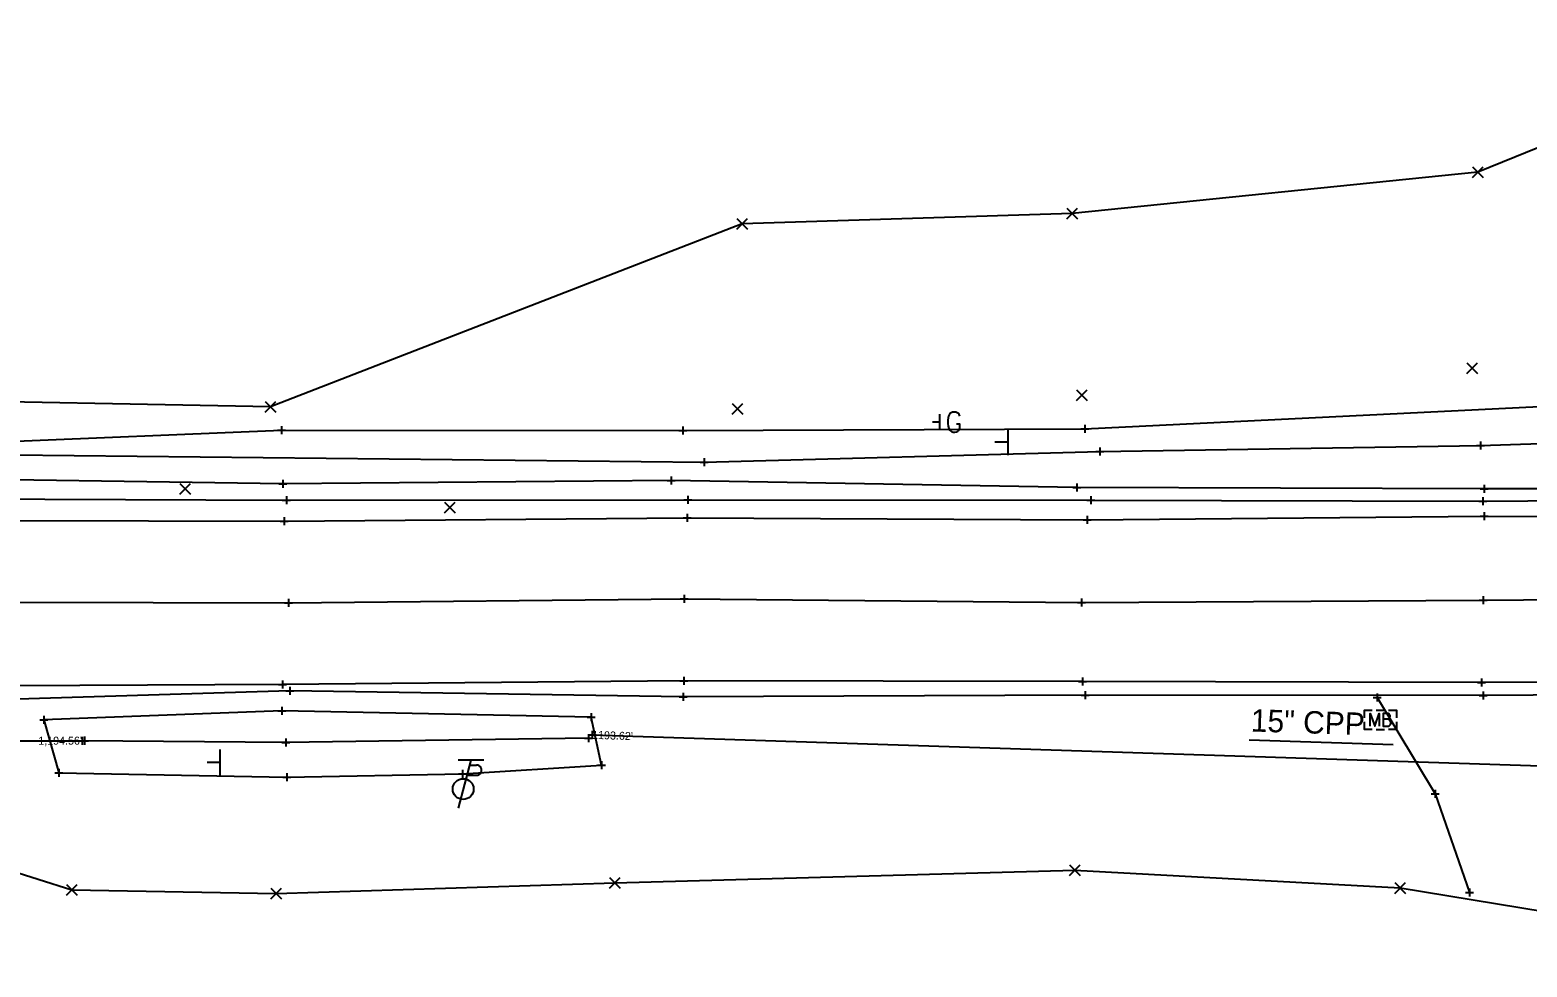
# Model space of a CAD drawing. Extents: x 2319153 to 2321514, y 575338 to 575500.
# Drawn here: x 2320483 to 2320670.1, y 575366.1 to 575483.2 of the extents above; entities that cross this region are included whole.
import ezdxf

# ---------------------------------------------------------------- set-up
doc = ezdxf.new("R2010")
doc.units = 0
for name, color, linetype in [('Default', 7, 'Continuous'), ('DR_X_Ditch', 7, 'Continuous'), ('DR_X_Elev_Flow', 7, 'Continuous'), ('DR_X_Storm_Sewer', 7, 'Continuous'), ('DR_X_Text', 7, 'Continuous'), ('PV_X_COP', 7, 'Continuous'), ('PV_X_Driveway', 7, 'Continuous'), ('PV_X_EOP', 7, 'Continuous'), ('PV_X_Shoulder', 7, 'Continuous'), ('RD_X_Cells', 7, 'Continuous'), ('SC_Scratch1', 7, 'Continuous'), ('SN_X_Public', 7, 'Continuous'), ('SV_X_Break_Lines', 7, 'Continuous'), ('SV_X_Random_Point', 7, 'Continuous'), ('SV_X_Shot_Marker', 7, 'Continuous'), ('SV_X_Terrain_Boundary', 7, 'Continuous'), ('UT_X_Gas_Cells', 7, 'Continuous'), ('UT_X_Misc_Cells', 7, 'Continuous')]:
    doc.layers.add(name, color=color, linetype=linetype)

msp = doc.modelspace()

# ---------------------------------------------------------------- linework, layer by layer
at = {"layer": 'Default'}
msp.add_line((2320553.26, 575395.15), (2320553.26, 575395.15), dxfattribs=at)
at = {"layer": 'DR_X_Ditch'}
for points in [[(2320442.27, 575427.97), (2320464.89, 575430.3), (2320567.27, 575429.23), (2320616.67, 575430.56), (2320664.25, 575431.29), (2320715.69, 575433.03), (2320722.62, 575480.62)], [(2320552.81, 575394.74), (2320515, 575394.2), (2320489.55, 575394.38)]]:
    msp.add_lwpolyline(points, dxfattribs=at)
at = {"layer": 'DR_X_Elev_Flow'}
for p, q in [((2320489.84, 575394.92), (2320489.84, 575393.92)), ((2320552.76, 575395.15), (2320553.76, 575395.15)), ((2320553.26, 575395.65), (2320553.26, 575394.65)), ((2320553.26, 575395.15), (2320553.26, 575395.15)), ((2320489.34, 575394.42), (2320490.34, 575394.42)), ((2320489.84, 575394.42), (2320489.84, 575394.42))]:
    msp.add_line(p, q, dxfattribs=at)
at = {"layer": 'DR_X_Storm_Sewer'}
for p, q in [((2320553.26, 575395.15), (2320731.3, 575389.3)), ((2320445.01, 575394.3), (2320489.84, 575394.42))]:
    msp.add_line(p, q, dxfattribs=at)
at = {"layer": 'DR_X_Text'}
msp.add_line((2320653.33, 575393.89), (2320635.36, 575394.48), dxfattribs=at)
at = {"layer": 'PV_X_COP'}
msp.add_lwpolyline([(2320114.93, 575411.33), (2320165.7, 575411.06), (2320216.04, 575411.34), (2320265.84, 575411.19), (2320315.14, 575411.25), (2320365.04, 575411.47), (2320415.78, 575411.96), (2320464.61, 575411.79), (2320515.32, 575411.65), (2320564.75, 575412.16), (2320614.38, 575411.69), (2320664.58, 575411.98), (2320714.9, 575412.38)], dxfattribs=at)
at = {"layer": 'PV_X_Driveway'}
msp.add_lwpolyline([(2320651.34, 575399.8), (2320658.59, 575387.79), (2320662.88, 575375.45)], dxfattribs=at)
at = {"layer": 'PV_X_EOP'}
for points in [[(2320093.83, 575421.33), (2320165.53, 575421.34), (2320217.08, 575420.91), (2320266.56, 575421.33), (2320315.91, 575421.64), (2320365.38, 575421.59), (2320416.21, 575421.87), (2320463.92, 575421.98), (2320514.77, 575421.86), (2320565.11, 575422.28), (2320615.12, 575422), (2320664.7, 575422.48), (2320715.11, 575422.41)], [(2320714.4, 575401.87), (2320664.35, 575401.67), (2320614.5, 575401.81), (2320564.7, 575401.89), (2320514.59, 575401.42), (2320463.88, 575401.2), (2320414.8, 575400.99), (2320364.6, 575400.96), (2320315.2, 575400.77), (2320265.49, 575400.71), (2320215.68, 575400.77), (2320165.34, 575400.63), (2320115.4, 575400.66)]]:
    msp.add_lwpolyline(points, dxfattribs=at)
at = {"layer": 'PV_X_Shoulder'}
for points in [[(2320077.57, 575423.62), (2320166.34, 575422.88), (2320218.2, 575423.13), (2320266.92, 575423.62), (2320316.5, 575423.54), (2320365.74, 575423.49), (2320415.91, 575423.76), (2320464.74, 575424.68), (2320515.05, 575424.47), (2320565.23, 575424.51), (2320615.54, 575424.46), (2320664.52, 575424.33), (2320715.19, 575424.71)], [(2320714.58, 575400.4), (2320664.56, 575400.05), (2320614.84, 575400.09), (2320564.64, 575399.89), (2320515.49, 575400.65), (2320463.79, 575399.05), (2320414.96, 575398.83), (2320364.78, 575399.66), (2320315.61, 575399.52), (2320265.3, 575399.56), (2320215.74, 575399.78), (2320165.72, 575399.22), (2320115.8, 575398.99)]]:
    msp.add_lwpolyline(points, dxfattribs=at)
at = {"layer": 'RD_X_Cells'}
for p, q in [((2320651.22, 575398.24), (2320652.23, 575398.24)), ((2320651.74, 575397.02), (2320651.74, 575397.02)), ((2320651.22, 575395.8), (2320652.23, 575395.8))]:
    msp.add_line(p, q, dxfattribs=at)
for points in [[(2320649.74, 575397.27), (2320649.74, 575398.24), (2320650.71, 575398.24)], [(2320650.71, 575395.8), (2320649.74, 575395.8), (2320649.74, 575396.77)], [(2320650.44, 575396.22), (2320650.44, 575397.82), (2320651.02, 575396.22), (2320651.57, 575397.82), (2320651.57, 575396.22)], [(2320652.76, 575397.09), (2320652.82, 575397.15), (2320652.86, 575397.19), (2320652.88, 575397.23), (2320652.9, 575397.25), (2320652.92, 575397.31), (2320652.93, 575397.34), (2320652.96, 575397.43), (2320652.96, 575397.47), (2320652.96, 575397.52), (2320652.95, 575397.59), (2320652.92, 575397.66), (2320652.88, 575397.71), (2320652.82, 575397.76), (2320652.77, 575397.78), (2320652.75, 575397.8), (2320652.68, 575397.82), (2320652.07, 575397.82), (2320652.07, 575396.22), (2320652.76, 575396.22), (2320652.85, 575396.27), (2320652.92, 575396.34), (2320652.98, 575396.44), (2320653.02, 575396.55), (2320653.04, 575396.66), (2320653.04, 575396.74), (2320653.01, 575396.81), (2320652.96, 575396.93), (2320652.9, 575397), (2320652.76, 575397.09), (2320652.07, 575397.09)], [(2320652.74, 575398.24), (2320653.74, 575398.24), (2320653.74, 575397.27)], [(2320653.74, 575396.77), (2320653.74, 575395.8), (2320652.74, 575395.8)]]:
    msp.add_lwpolyline(points, dxfattribs=at)
at = {"layer": 'SN_X_Public'}
for p, q in [((2320605.18, 575433.31), (2320605.18, 575430.11)), ((2320605.18, 575431.71), (2320603.58, 575431.71)), ((2320506.74, 575393.31), (2320506.74, 575390.11)), ((2320506.74, 575391.71), (2320505.14, 575391.71))]:
    msp.add_line(p, q, dxfattribs=at)
at = {"layer": 'SV_X_Break_Lines'}
msp.add_lwpolyline([(2320732.93, 575442.06), (2320727.34, 575431.55), (2320720.41, 575425.89), (2320664.7, 575425.9), (2320613.83, 575426.05), (2320563.12, 575426.93), (2320514.6, 575426.5), (2320463.64, 575427.26), (2320441.18, 575426.16), (2320442.02, 575430.24), (2320514.44, 575433.22), (2320564.58, 575433.19), (2320614.81, 575433.37), (2320685.2, 575436.83)], dxfattribs=at)
msp.add_lwpolyline([(2320486.63, 575390.39), (2320515.13, 575389.87), (2320537.05, 575390.29), (2320554.44, 575391.36), (2320553.12, 575397.36), (2320514.47, 575398.15), (2320484.75, 575397.04)], close=True, dxfattribs=at)
at = {"layer": 'SV_X_Random_Point'}
for p, q in [((2320663.23, 575464.81), (2320664.57, 575466.14)), ((2320663.23, 575466.14), (2320664.57, 575464.81)), ((2320612.56, 575459.64), (2320613.89, 575460.97)), ((2320612.56, 575460.97), (2320613.89, 575459.64)), ((2320571.34, 575458.34), (2320572.68, 575459.68)), ((2320571.34, 575459.68), (2320572.68, 575458.34)), ((2320662.55, 575440.29), (2320663.88, 575441.63)), ((2320662.55, 575441.63), (2320663.88, 575440.29)), ((2320613.78, 575436.92), (2320615.12, 575438.25)), ((2320613.78, 575438.25), (2320615.12, 575436.92)), ((2320512.39, 575435.47), (2320513.73, 575436.8)), ((2320512.39, 575436.8), (2320513.73, 575435.47)), ((2320570.75, 575435.22), (2320572.08, 575436.56)), ((2320570.75, 575436.56), (2320572.08, 575435.22)), ((2320501.75, 575425.21), (2320503.08, 575426.54)), ((2320501.75, 575426.54), (2320503.08, 575425.21)), ((2320534.79, 575422.89), (2320536.13, 575424.23)), ((2320534.79, 575424.23), (2320536.13, 575422.89)), ((2320612.9, 575377.59), (2320614.24, 575378.92)), ((2320612.9, 575378.92), (2320614.24, 575377.59)), ((2320487.58, 575375.11), (2320488.92, 575376.45)), ((2320487.58, 575376.45), (2320488.92, 575375.11)), ((2320555.41, 575376), (2320556.74, 575377.33)), ((2320555.41, 575377.33), (2320556.74, 575376)), ((2320653.54, 575375.34), (2320654.87, 575376.68)), ((2320653.54, 575376.68), (2320654.87, 575375.34)), ((2320513.11, 575374.66), (2320514.44, 575376)), ((2320513.11, 575376), (2320514.44, 575374.66))]:
    msp.add_line(p, q, dxfattribs=at)
at = {"layer": 'SV_X_Shot_Marker'}
for p, q in [((2320513.94, 575433.22), (2320514.94, 575433.22)), ((2320514.44, 575433.72), (2320514.44, 575432.72)), ((2320514.44, 575433.22), (2320514.44, 575433.22)), ((2320564.08, 575433.19), (2320565.08, 575433.19)), ((2320564.58, 575433.69), (2320564.58, 575432.69)), ((2320564.58, 575433.19), (2320564.58, 575433.19)), ((2320614.31, 575433.37), (2320615.31, 575433.37)), ((2320614.81, 575433.87), (2320614.81, 575432.87)), ((2320614.81, 575433.37), (2320614.81, 575433.37)), ((2320616.17, 575430.56), (2320617.17, 575430.56)), ((2320616.67, 575431.06), (2320616.67, 575430.06)), ((2320616.67, 575430.56), (2320616.67, 575430.56)), ((2320663.75, 575431.29), (2320664.75, 575431.29)), ((2320664.25, 575431.79), (2320664.25, 575430.79)), ((2320664.25, 575431.29), (2320664.25, 575431.29)), ((2320566.77, 575429.23), (2320567.77, 575429.23)), ((2320567.27, 575429.73), (2320567.27, 575428.73)), ((2320567.27, 575429.23), (2320567.27, 575429.23)), ((2320514.6, 575427), (2320514.6, 575426)), ((2320562.62, 575426.93), (2320563.62, 575426.93)), ((2320563.12, 575427.43), (2320563.12, 575426.43)), ((2320563.12, 575426.93), (2320563.12, 575426.93)), ((2320514.1, 575426.5), (2320515.1, 575426.5)), ((2320514.6, 575426.5), (2320514.6, 575426.5)), ((2320515.05, 575424.97), (2320515.05, 575423.97)), ((2320565.23, 575425.01), (2320565.23, 575424.01)), ((2320613.33, 575426.05), (2320614.33, 575426.05)), ((2320613.83, 575426.55), (2320613.83, 575425.55)), ((2320613.83, 575426.05), (2320613.83, 575426.05)), ((2320615.54, 575424.96), (2320615.54, 575423.96)), ((2320664.2, 575425.9), (2320665.2, 575425.9)), ((2320664.52, 575424.83), (2320664.52, 575423.83)), ((2320664.7, 575426.4), (2320664.7, 575425.4)), ((2320664.7, 575425.9), (2320664.7, 575425.9)), ((2320514.55, 575424.47), (2320515.55, 575424.47)), ((2320515.05, 575424.47), (2320515.05, 575424.47)), ((2320564.73, 575424.51), (2320565.73, 575424.51)), ((2320565.23, 575424.51), (2320565.23, 575424.51)), ((2320615.04, 575424.46), (2320616.04, 575424.46)), ((2320615.54, 575424.46), (2320615.54, 575424.46)), ((2320664.02, 575424.33), (2320665.02, 575424.33)), ((2320664.52, 575424.33), (2320664.52, 575424.33)), ((2320664.7, 575422.98), (2320664.7, 575421.98)), ((2320514.27, 575421.86), (2320515.27, 575421.86)), ((2320514.77, 575422.36), (2320514.77, 575421.36)), ((2320514.77, 575421.86), (2320514.77, 575421.86)), ((2320564.61, 575422.28), (2320565.61, 575422.28)), ((2320565.11, 575422.78), (2320565.11, 575421.78)), ((2320565.11, 575422.28), (2320565.11, 575422.28)), ((2320614.62, 575422), (2320615.62, 575422)), ((2320615.12, 575422.5), (2320615.12, 575421.5)), ((2320615.12, 575422), (2320615.12, 575422)), ((2320664.2, 575422.48), (2320665.2, 575422.48)), ((2320664.7, 575422.48), (2320664.7, 575422.48)), ((2320515.32, 575412.15), (2320515.32, 575411.15)), ((2320564.25, 575412.16), (2320565.25, 575412.16)), ((2320564.75, 575412.66), (2320564.75, 575411.66)), ((2320564.75, 575412.16), (2320564.75, 575412.16)), ((2320613.88, 575411.69), (2320614.88, 575411.69)), ((2320614.38, 575412.19), (2320614.38, 575411.19)), ((2320614.38, 575411.69), (2320614.38, 575411.69)), ((2320664.08, 575411.98), (2320665.08, 575411.98)), ((2320664.58, 575412.48), (2320664.58, 575411.48)), ((2320664.58, 575411.98), (2320664.58, 575411.98)), ((2320514.82, 575411.65), (2320515.82, 575411.65)), ((2320515.32, 575411.65), (2320515.32, 575411.65)), ((2320564.7, 575402.39), (2320564.7, 575401.39)), ((2320614.5, 575402.31), (2320614.5, 575401.31)), ((2320514.09, 575401.42), (2320515.09, 575401.42)), ((2320514.59, 575401.92), (2320514.59, 575400.92)), ((2320514.59, 575401.42), (2320514.59, 575401.42)), ((2320514.99, 575400.65), (2320515.99, 575400.65)), ((2320515.49, 575401.15), (2320515.49, 575400.15)), ((2320515.49, 575400.65), (2320515.49, 575400.65)), ((2320564.2, 575401.89), (2320565.2, 575401.89)), ((2320564.7, 575401.89), (2320564.7, 575401.89)), ((2320614, 575401.81), (2320615, 575401.81)), ((2320614.5, 575401.81), (2320614.5, 575401.81)), ((2320614.84, 575400.59), (2320614.84, 575399.59)), ((2320663.85, 575401.67), (2320664.85, 575401.67)), ((2320664.35, 575402.17), (2320664.35, 575401.17)), ((2320664.35, 575401.67), (2320664.35, 575401.67)), ((2320664.56, 575400.55), (2320664.56, 575399.55)), ((2320514.47, 575398.65), (2320514.47, 575397.65)), ((2320564.14, 575399.89), (2320565.14, 575399.89)), ((2320564.64, 575400.39), (2320564.64, 575399.39)), ((2320564.64, 575399.89), (2320564.64, 575399.89)), ((2320614.34, 575400.09), (2320615.34, 575400.09)), ((2320614.84, 575400.09), (2320614.84, 575400.09)), ((2320650.84, 575399.8), (2320651.84, 575399.8)), ((2320651.34, 575400.3), (2320651.34, 575399.3)), ((2320651.34, 575399.8), (2320651.34, 575399.8)), ((2320664.06, 575400.05), (2320665.06, 575400.05)), ((2320664.56, 575400.05), (2320664.56, 575400.05)), ((2320484.25, 575397.04), (2320485.25, 575397.04)), ((2320484.75, 575397.54), (2320484.75, 575396.54)), ((2320484.75, 575397.04), (2320484.75, 575397.04)), ((2320513.97, 575398.15), (2320514.97, 575398.15)), ((2320514.47, 575398.15), (2320514.47, 575398.15)), ((2320552.62, 575397.36), (2320553.62, 575397.36)), ((2320553.12, 575397.86), (2320553.12, 575396.86)), ((2320553.12, 575397.36), (2320553.12, 575397.36)), ((2320489.55, 575394.88), (2320489.55, 575393.88)), ((2320552.81, 575395.24), (2320552.81, 575394.24)), ((2320489.05, 575394.38), (2320490.05, 575394.38)), ((2320489.55, 575394.38), (2320489.55, 575394.38)), ((2320514.5, 575394.2), (2320515.5, 575394.2)), ((2320515, 575394.7), (2320515, 575393.7)), ((2320515, 575394.2), (2320515, 575394.2)), ((2320552.31, 575394.74), (2320553.31, 575394.74)), ((2320552.81, 575394.74), (2320552.81, 575394.74)), ((2320553.94, 575391.36), (2320554.94, 575391.36)), ((2320554.44, 575391.86), (2320554.44, 575390.86)), ((2320554.44, 575391.36), (2320554.44, 575391.36)), ((2320486.13, 575390.39), (2320487.13, 575390.39)), ((2320486.63, 575390.89), (2320486.63, 575389.89)), ((2320486.63, 575390.39), (2320486.63, 575390.39)), ((2320514.63, 575389.87), (2320515.63, 575389.87)), ((2320515.13, 575390.37), (2320515.13, 575389.37)), ((2320515.13, 575389.87), (2320515.13, 575389.87)), ((2320536.55, 575390.29), (2320537.55, 575390.29)), ((2320537.05, 575390.79), (2320537.05, 575389.79)), ((2320537.05, 575390.29), (2320537.05, 575390.29)), ((2320658.09, 575387.79), (2320659.09, 575387.79)), ((2320658.59, 575388.29), (2320658.59, 575387.29)), ((2320658.59, 575387.79), (2320658.59, 575387.79)), ((2320662.38, 575375.45), (2320663.38, 575375.45)), ((2320662.88, 575375.95), (2320662.88, 575374.95)), ((2320662.88, 575375.45), (2320662.88, 575375.45))]:
    msp.add_line(p, q, dxfattribs=at)
at = {"layer": 'SV_X_Terrain_Boundary'}
for points in [[(2320707.74, 575483.24), (2320663.9, 575465.47), (2320613.22, 575460.31), (2320572.01, 575459.01), (2320513.06, 575436.13), (2320464.78, 575437.07), (2320435.13, 575443.06), (2320425.54, 575442.92), (2320413.45, 575444.77), (2320365.74, 575423.49), (2320316.5, 575423.54), (2320266.92, 575423.62), (2320218.2, 575423.13), (2320166.34, 575422.88), (2320077.57, 575423.62)], [(2320077.57, 575423.62), (2320093.83, 575421.33), (2320114.93, 575411.33), (2320115.4, 575400.66), (2320115.8, 575398.99), (2320165.72, 575399.22), (2320215.74, 575399.78), (2320265.3, 575399.56), (2320315.61, 575399.52), (2320364.78, 575399.66), (2320412.19, 575377.5), (2320462.72, 575376.55), (2320467.54, 575377.42), (2320479.84, 575378.43), (2320488.25, 575375.78), (2320513.78, 575375.33), (2320556.07, 575376.66), (2320613.57, 575378.25), (2320654.2, 575376.01), (2320714.52, 575366.13)]]:
    msp.add_lwpolyline(points, dxfattribs=at)
at = {"layer": 'UT_X_Gas_Cells'}
for p, q in [((2320596.71, 575434.23), (2320595.76, 575434.23)), ((2320596.71, 575433.23), (2320596.71, 575435.23))]:
    msp.add_line(p, q, dxfattribs=at)
msp.add_lwpolyline([(2320599.19, 575434.99), (2320599.17, 575435.09), (2320599.11, 575435.19), (2320599.01, 575435.29), (2320598.87, 575435.4), (2320598.78, 575435.44), (2320598.7, 575435.46), (2320598.58, 575435.48), (2320598.34, 575435.48), (2320598.25, 575435.46), (2320598.19, 575435.44), (2320598.11, 575435.4), (2320597.95, 575435.29), (2320597.85, 575435.15), (2320597.79, 575434.99), (2320597.75, 575434.77), (2320597.71, 575434.46), (2320597.71, 575434.05), (2320597.73, 575433.71), (2320597.81, 575433.45), (2320597.93, 575433.22), (2320598.03, 575433.14), (2320598.15, 575433.06), (2320598.36, 575432.98), (2320598.58, 575432.98), (2320598.8, 575433.02), (2320598.87, 575433.06), (2320598.95, 575433.1), (2320599.03, 575433.18), (2320599.11, 575433.3), (2320599.19, 575433.47), (2320599.19, 575433.97), (2320598.78, 575433.97)], dxfattribs=at)
at = {"layer": 'UT_X_Misc_Cells'}
for p, q in [((2320538.11, 575391.97), (2320536.5, 575385.97)), ((2320539.71, 575391.97), (2320536.51, 575391.97)), ((2320537.95, 575391.37), (2320538.8, 575391.37)), ((2320537.61, 575390.09), (2320538.8, 575390.09))]:
    msp.add_line(p, q, dxfattribs=at)
msp.add_circle((2320537.14, 575388.37), 1.3, dxfattribs=at)
msp.add_arc((2320538.81, 575390.73), 0.638, 268.8767, 91.1233, dxfattribs=at)

# ---------------------------------------------------------------- texts
at = {"layer": 'DR_X_Text'}
msp.add_text('15" CPP', height=2.8, rotation=358.1199, dxfattribs=at).set_placement((2320635.51, 575395.57))
at = {"layer": 'SC_Scratch1'}
for s, rotation, p in [("1,194.56'", 0.1614, (2320484.06, 575393.91)), ("1193.62'", 358.1199, (2320553.24, 575394.65))]:
    msp.add_text(s, height=1, rotation=rotation, dxfattribs=at).set_placement(p)

doc.saveas('drawing.dxf')
